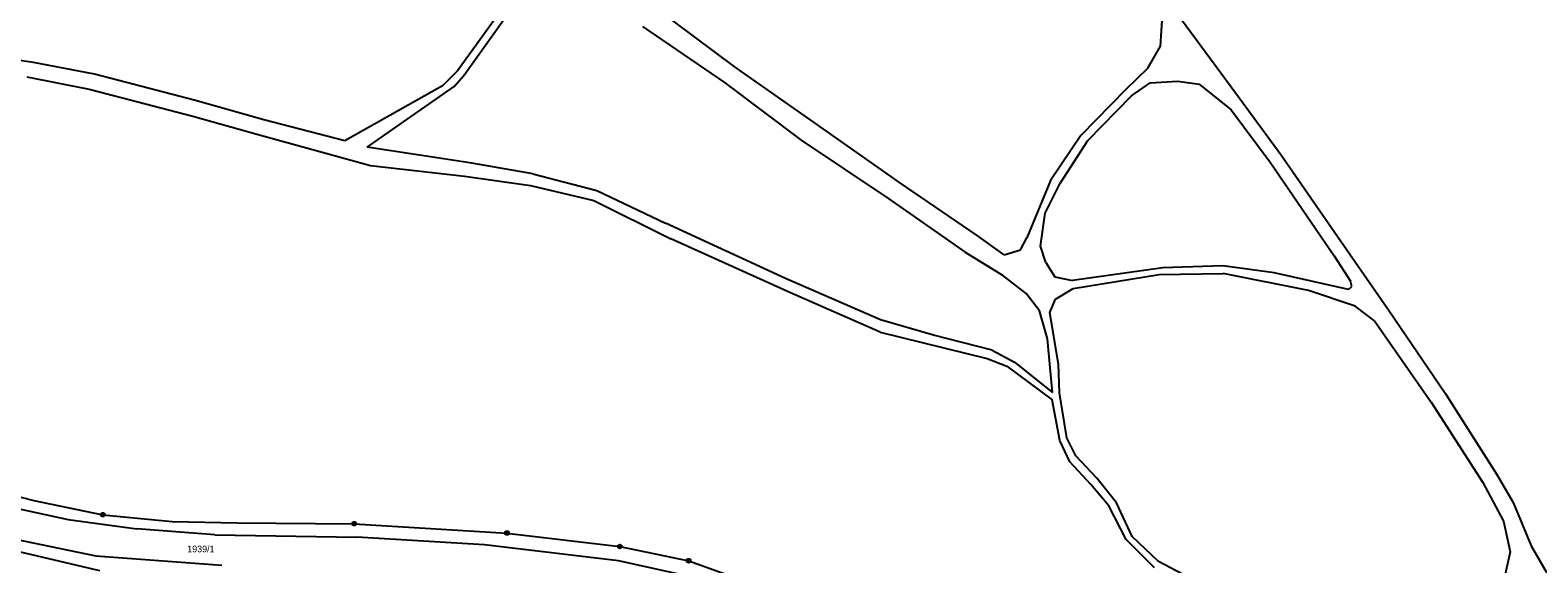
# Model space of a CAD drawing. Extents: x -795483 to -789093, y -1112258 to -1108741.
# Drawn here: x -792291.7 to -791907.6, y -1110713.5 to -1110577.6 of the extents above; entities that cross this region are included whole.
import ezdxf

# ---------------------------------------------------------------- set-up
doc = ezdxf.new("R2010")
doc.units = 0
for name, color, linetype in [('Vrstva 1', 7, 'Continuous'), ('Vrstva 14', 7, 'Continuous'), ('Vrstva 2', 7, 'Continuous'), ('Vrstva 28', 7, 'Continuous')]:
    doc.layers.add(name, color=color, linetype=linetype)

msp = doc.modelspace()

# ---------------------------------------------------------------- linework, layer by layer
at = {"layer": 'Vrstva 1'}
for p, q in [((-792302.13, -1110694.42), (-792290.77, -1110697.41)), ((-792290.77, -1110697.41), (-792273.17, -1110701)), ((-792273.17, -1110701), (-792255.5, -1110702.74)), ((-792255.5, -1110702.74), (-792238.91, -1110703.1)), ((-792238.91, -1110703.1), (-792209.13, -1110703.29)), ((-792209.13, -1110703.29), (-792170.2, -1110705.67)), ((-792170.2, -1110705.67), (-792141.44, -1110709.1)), ((-792302.25, -1110708.57), (-792274.02, -1110715.25)), ((-792141.44, -1110709.1), (-792123.92, -1110712.72)), ((-792123.92, -1110712.72), (-792101.44, -1110720.8))]:
    msp.add_line(p, q, dxfattribs=at)
at = {"layer": 'Vrstva 2'}
for p, q in [((-792166.86, -1110565.82), (-792182.83, -1110587.93)), ((-792181.17, -1110589.18), (-792165.27, -1110566.84)), ((-792112.1, -1110587.02), (-792132.78, -1110571.53)), ((-792001.02, -1110571.31), (-791984.49, -1110593.66)), ((-792003.73, -1110581.65), (-792003.2, -1110573.9)), ((-792135.69, -1110576.7), (-792114.79, -1110590.93)), ((-792290.86, -1110585.84), (-792311.16, -1110582.99)), ((-792006.98, -1110587.31), (-792003.73, -1110581.65)), ((-792275.31, -1110588.76), (-792290.86, -1110585.84)), ((-792182.83, -1110587.93), (-792186.6, -1110591.74)), ((-792091.93, -1110601.11), (-792112.1, -1110587.02)), ((-792006.98, -1110587.31), (-792012.54, -1110592.69)), ((-792292.51, -1110589.52), (-792276.64, -1110592.58)), ((-792249.54, -1110595.51), (-792275.31, -1110588.76)), ((-792186.6, -1110591.74), (-792211.49, -1110605.79)), ((-792183.67, -1110591.96), (-792181.17, -1110589.18)), ((-792114.79, -1110590.93), (-792095.25, -1110605.57)), ((-792011.14, -1110594.33), (-792006.38, -1110591.04)), ((-792006.38, -1110591.04), (-791999.27, -1110590.6)), ((-791999.27, -1110590.6), (-791993.84, -1110591.38)), ((-791993.84, -1110591.38), (-791985.68, -1110597.87)), ((-792276.64, -1110592.58), (-792250.2, -1110599.54)), ((-792232.12, -1110600.41), (-792249.54, -1110595.51)), ((-792205.81, -1110607.42), (-792183.67, -1110591.96)), ((-792012.54, -1110592.69), (-792023.98, -1110604.45)), ((-792022.21, -1110605.66), (-792011.14, -1110594.33)), ((-791984.49, -1110593.66), (-791973.04, -1110609.28)), ((-792250.2, -1110599.54), (-792233.62, -1110604.16)), ((-791985.68, -1110597.87), (-791975.76, -1110611.19)), ((-792211.49, -1110605.79), (-792232.12, -1110600.41)), ((-792070.17, -1110616.41), (-792091.93, -1110601.11)), ((-792233.62, -1110604.16), (-792205.01, -1110612.09)), ((-792095.25, -1110605.57), (-792072.92, -1110620.52)), ((-792023.98, -1110604.45), (-792031.77, -1110615.89)), ((-792029.33, -1110616.71), (-792022.21, -1110605.66)), ((-792179.12, -1110611.44), (-792205.81, -1110607.42)), ((-791973.04, -1110609.28), (-791956.29, -1110633.56)), ((-792205.01, -1110612.09), (-792181.05, -1110614.77)), ((-792181.05, -1110614.77), (-792164.24, -1110617.17)), ((-792163.62, -1110614.21), (-792179.12, -1110611.44)), ((-792163.62, -1110614.21), (-792147.3, -1110618.43)), ((-791975.76, -1110611.19), (-791959.51, -1110635.08)), ((-792164.24, -1110617.17), (-792148.09, -1110620.94)), ((-792147.3, -1110618.43), (-792129.81, -1110626.76)), ((-792050.46, -1110629.93), (-792070.17, -1110616.41)), ((-792031.77, -1110615.89), (-792037.75, -1110630.49)), ((-792033.1, -1110624.19), (-792029.33, -1110616.71)), ((-792148.09, -1110620.94), (-792128.44, -1110630.74)), ((-792072.92, -1110620.52), (-792053.51, -1110634.14)), ((-792034.29, -1110632.65), (-792033.1, -1110624.19)), ((-792099.26, -1110640.88), (-792129.81, -1110626.76)), ((-792043.59, -1110634.84), (-792050.46, -1110629.93)), ((-792098.01, -1110644.5), (-792128.44, -1110630.74)), ((-792053.51, -1110634.14), (-792044, -1110639.98)), ((-792043.59, -1110634.84), (-792039.37, -1110633.5)), ((-792039.37, -1110633.5), (-792037.75, -1110630.49)), ((-792032.93, -1110636.78), (-792034.29, -1110632.65)), ((-791956.29, -1110633.56), (-791945.51, -1110649.05)), ((-792032.93, -1110636.78), (-792030.67, -1110640.44)), ((-791987.87, -1110637.65), (-792003.16, -1110638.11)), ((-791974.75, -1110639.4), (-791987.87, -1110637.65)), ((-791959.51, -1110635.08), (-791955.32, -1110641.52)), ((-792075.05, -1110651.4), (-792099.26, -1110640.88)), ((-792037.97, -1110644.68), (-792044, -1110639.98)), ((-792030.67, -1110640.44), (-792026.15, -1110641.32)), ((-792003.16, -1110638.11), (-792026.15, -1110641.32)), ((-792025.97, -1110643.42), (-792004.06, -1110639.85)), ((-792004.06, -1110639.85), (-791987.73, -1110639.53)), ((-791966.04, -1110643.87), (-791987.73, -1110639.53)), ((-791955.8, -1110643.64), (-791974.75, -1110639.4)), ((-791954.96, -1110642.86), (-791955.32, -1110641.52)), ((-792075.17, -1110654.54), (-792098.01, -1110644.5)), ((-792034.57, -1110649.05), (-792037.97, -1110644.68)), ((-792030.48, -1110646.09), (-792025.97, -1110643.42)), ((-791954.17, -1110647.88), (-791966.04, -1110643.87)), ((-791955.8, -1110643.64), (-791954.96, -1110642.86)), ((-792032.54, -1110656.24), (-792034.57, -1110649.05)), ((-792031.93, -1110649.52), (-792030.48, -1110646.09)), ((-792029.73, -1110662.62), (-792031.93, -1110649.52)), ((-791949.19, -1110651.62), (-791954.17, -1110647.88)), ((-791945.51, -1110649.05), (-791931.18, -1110670.01)), ((-792061.53, -1110655.28), (-792075.05, -1110651.4)), ((-791949.19, -1110651.62), (-791934.77, -1110672.31)), ((-792075.17, -1110654.54), (-792047.85, -1110661.19)), ((-792046.63, -1110659.1), (-792061.53, -1110655.28)), ((-792031.85, -1110663.56), (-792032.54, -1110656.24)), ((-792046.63, -1110659.1), (-792040.89, -1110662.15)), ((-792047.85, -1110661.19), (-792042.85, -1110663.14)), ((-792042.85, -1110663.14), (-792031.35, -1110671.78)), ((-792040.89, -1110662.15), (-792031.2, -1110669.91)), ((-792031.2, -1110669.91), (-792031.85, -1110663.56)), ((-792029.44, -1110669.93), (-792029.73, -1110662.62)), ((-792029.37, -1110682.12), (-792031.35, -1110671.78)), ((-792027.59, -1110681.39), (-792029.44, -1110669.93)), ((-791934.77, -1110672.31), (-791921.61, -1110692.76)), ((-791931.18, -1110670.01), (-791918.05, -1110690.76)), ((-792026.84, -1110687.52), (-792029.37, -1110682.12)), ((-792025.33, -1110686.04), (-792027.59, -1110681.39)), ((-792021.49, -1110693.29), (-792026.84, -1110687.52)), ((-792019.96, -1110691.67), (-792025.33, -1110686.04)), ((-792014.92, -1110698.02), (-792019.96, -1110691.67)), ((-791918.05, -1110690.76), (-791913.9, -1110697.87)), ((-792016.9, -1110698.75), (-792021.49, -1110693.29)), ((-791921.61, -1110692.76), (-791916.35, -1110702.65)), ((-792300.64, -1110698.15), (-792281.95, -1110702.26)), ((-792012.46, -1110707.36), (-792016.9, -1110698.75)), ((-792010.94, -1110706.52), (-792014.92, -1110698.02)), ((-791913.9, -1110697.87), (-791909.26, -1110708.94)), ((-792281.95, -1110702.26), (-792264.49, -1110704.57)), ((-791916.35, -1110702.65), (-791914.61, -1110710.49)), ((-792302.49, -1110705.82), (-792274.94, -1110711.46)), ((-792244.62, -1110706.17), (-792264.49, -1110704.57)), ((-792244.62, -1110706.17), (-792208.46, -1110706.72)), ((-792175.95, -1110708.64), (-792208.46, -1110706.72)), ((-792004.25, -1110712.9), (-792010.94, -1110706.52)), ((-792141.82, -1110712.78), (-792175.95, -1110708.64)), ((-792005.29, -1110714.54), (-792012.46, -1110707.36)), ((-791914.61, -1110710.49), (-791916.24, -1110717.65)), ((-791909.26, -1110708.94), (-791905.25, -1110715.98)), ((-792274.94, -1110711.46), (-792242.84, -1110713.89)), ((-792122.98, -1110716.95), (-792141.82, -1110712.78)), ((-791995.02, -1110717.8), (-792004.25, -1110712.9))]:
    msp.add_line(p, q, dxfattribs=at)
at = {"layer": 'Vrstva 28'}
for centre, radius in [((-792273.17, -1110701), 0.5), ((-792273.17, -1110701), 0.01), ((-792209.13, -1110703.29), 0.5), ((-792209.13, -1110703.29), 0.01), ((-792170.2, -1110705.67), 0.5), ((-792170.2, -1110705.67), 0.01), ((-792141.44, -1110709.1), 0.5), ((-792141.44, -1110709.1), 0.01), ((-792123.92, -1110712.72), 0.5), ((-792123.92, -1110712.72), 0.01)]:
    msp.add_circle(centre, radius, dxfattribs=at)

# ---------------------------------------------------------------- texts
at = {"layer": 'Vrstva 14'}
msp.add_text('1939/1', height=1.7, dxfattribs=at).set_placement((-792251.66, -1110710.57))

doc.saveas('drawing.dxf')
